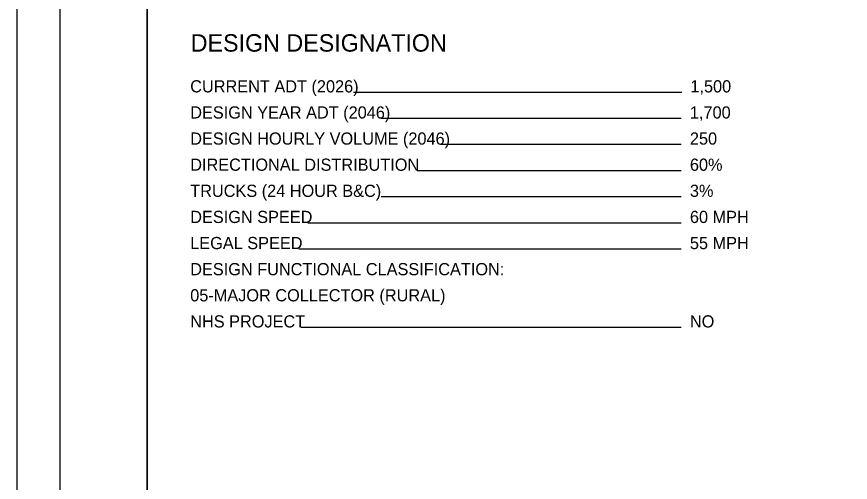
# Model space of a CAD drawing. Extents: x 0 to 34, y 0 to 22.
# Drawn here: x 0 to 9.58, y 5.53 to 10.88 of the extents above; entities that cross this region are included whole.
import ezdxf

# ---------------------------------------------------------------- set-up
doc = ezdxf.new("R2010")
doc.units = 0
for name, color, linetype in [('SH_Border', 7, 'Continuous'), ('SH_Cut_Line', 7, 'Continuous'), ('SH_Data', 7, 'Continuous'), ('SH_Text', 7, 'Continuous')]:
    doc.layers.add(name, color=color, linetype=linetype)

msp = doc.modelspace()

# ---------------------------------------------------------------- linework, layer by layer
at = {"layer": 'SH_Border'}
for points in [[(0.5, 21.5), (1.5, 21.5), (1.5, 0.5), (0.5, 0.5)], [(1.5, 21.5), (33.5, 21.5), (33.5, 0.5), (1.5, 0.5)]]:
    msp.add_lwpolyline(points, close=True, dxfattribs=at)
at = {"layer": 'SH_Cut_Line'}
msp.add_lwpolyline([(0, 0), (34, 0), (34, 22), (0, 22)], close=True, dxfattribs=at)
at = {"layer": 'SH_Data'}
for p, q in [((7.6424, 10.0062), (3.871, 10.0062)), ((7.6368, 9.7062), (4.1885, 9.7062)), ((7.6368, 9.4062), (4.8723, 9.4062)), ((7.6368, 9.1062), (4.6037, 9.1062)), ((7.6368, 8.8062), (4.1885, 8.8062)), ((7.6368, 8.5062), (3.346, 8.5062)), ((7.6368, 8.2062), (3.2422, 8.2062)), ((7.6368, 7.3062), (3.2669, 7.3062))]:
    msp.add_line(p, q, dxfattribs=at)

# ---------------------------------------------------------------- texts
msp.add_text('DESIGN DESIGNATION', height=0.2, dxfattribs=at).set_placement((2, 10.4747))
at = {"layer": 'SH_Text'}
for s, p in [('CURRENT ADT (2026)', (1.9944, 10.0062)), ('1,500', (7.7424, 10.0062)), ('DESIGN YEAR ADT (2046)', (1.9944, 9.7062)), ('1,700', (7.7368, 9.7062)), ('DESIGN HOURLY VOLUME (2046)', (1.9944, 9.4062)), ('250', (7.7368, 9.4062)), ('DIRECTIONAL DISTRIBUTION', (1.9944, 9.1062)), ('60%', (7.7368, 9.1062)), ('TRUCKS (24 HOUR B&C)', (1.9944, 8.8062)), ('3%', (7.7368, 8.8062)), ('DESIGN SPEED', (1.9944, 8.5062)), ('60 MPH', (7.7368, 8.5062)), ('LEGAL SPEED', (1.9944, 8.2062)), ('55 MPH', (7.7368, 8.2062)), ('DESIGN FUNCTIONAL CLASSIFICATION:', (1.9944, 7.9062)), ('05-MAJOR COLLECTOR (RURAL)', (1.9944, 7.6062)), ('NHS PROJECT', (1.9944, 7.3062)), ('NO', (7.7368, 7.3062))]:
    msp.add_text(s, height=0.14, dxfattribs=at).set_placement(p)

doc.saveas('drawing.dxf')
